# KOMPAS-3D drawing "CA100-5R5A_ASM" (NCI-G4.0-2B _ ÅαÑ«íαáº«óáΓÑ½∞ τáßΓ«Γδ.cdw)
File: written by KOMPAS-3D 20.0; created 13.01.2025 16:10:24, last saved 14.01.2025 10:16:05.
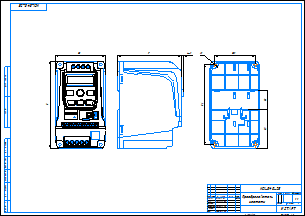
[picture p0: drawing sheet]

Sheet 1: A2, landscape

Document properties: Автор: admin; Полное имя файла: C:\Уралов Работа\Уралов (локальная)\ПЧ\! Китай 3Д-модель NCI\NCI 4.0-7.5 4B\NCI 4.0-7.5 4B.a3d

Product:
- Part/product: CA100-5R5A_ASM
    Масса: 7.13181
    Комментарий: NOT SPECIFIED
  - Component [detail]: CA100-5R5A-SR-01  | Масса: 0.808548; source file: C:\Уралов Работа\Уралов (локальная)\ПЧ\! Китай 3Д-модель NCI\NCI 4.0-7.5 4B\CA100-5R5A-SR-01.m3d
  - Component [detail]: CA100-4R0A-SR-01  | Масса: 0.923365; source file: C:\Уралов Работа\Уралов (локальная)\ПЧ\! Китай 3Д-модель NCI\NCI 4.0-7.5 4B\CA100-4R0A-SR-01.m3d
  - Component [assembly]: QJ_ASM  | Масса: 0.208727; source file: C:\Уралов Работа\Уралов (локальная)\ПЧ\! Китай 3Д-модель NCI\NCI 4.0-7.5 4B\QJ_ASM.a3d
  - Component [assembly]: PCB_ASM  | Масса: 1.9346; source file: C:\Уралов Работа\Уралов (локальная)\ПЧ\! Китай 3Д-модель NCI\NCI 4.0-7.5 4B\PCB_ASM.a3d
  - Component [assembly]: CA100-5R5A-SJ_ASM  | Масса: 1.6976; Комментарий: NOT SPECIFIED; source file: C:\Уралов Работа\Уралов (локальная)\ПЧ\! Китай 3Д-модель NCI\NCI 4.0-7.5 4B\CA100-5R5A-SJ_ASM.a3d
  - Component [assembly]: JIANPAN99_ASM_ASM  | Масса: 0.107178; Комментарий: NOT SPECIFIED; source file: C:\Уралов Работа\Уралов (локальная)\ПЧ\! Китай 3Д-модель NCI\NCI 4.0-7.5 4B\JIANPAN99_ASM_ASM.a3d
  - Component [detail]: CA100-2R2A-SJ-04  | Масса: 0.00516082; source file: C:\Уралов Работа\Уралов (локальная)\ПЧ\! Китай 3Д-модель NCI\NCI 4.0-7.5 4B\CA100-2R2A-SJ-04.m3d
  - Component [detail]: AA  | Масса: 1.44663; source file: C:\Уралов Работа\Уралов (локальная)\ПЧ\! Китай 3Д-модель NCI\NCI 4.0-7.5 4B\AA.m3d

Title block, sheet 1: Наименование: Преобразователь / частоты; designation: NCI-G4.0-2B; Количество листов документа: 1; organisation: INSTART; cell 10: Согласовано; Форматы листов документа: A2; stored path: P:\INSTART\Технический отдел\ОР\Прочие задачи\КД на номенклатурный ряд\КД на типоразмеры ПЧ\NCI\NCI-...-4B\NCI-G4.0_P5.5-4B\NCI-G4.0_P5.5-4B _ Преобразователь частоты.cdw; Разработал: Уралов Д.А.; Проверил: Андреев Н.В.; Подписал: Смелков Ж.Е.; Утвердил: Ефремов И.Н.; Разработал, date: 13.01.25

Views: Вид 1, Проекционный вид 2
Referenced files in C:\Уралов Работа\Уралов (локальная)\ПЧ\! Китай 3Д-модель NCI\NCI 4.0-7.5 4B\: CA100-4R0A-SR-01.m3d, CA100-5R5A-SR-01.m3d, 6025.m3d, QJ_ASM.a3d, QDB.m3d, DRI.m3d, 6912184100XX_MASS.m3d, 6912184100XX_PIN.m3d, 6912184100XX_VIS.m3d, 691218410003.m3d, ASSEM1_ASM.a3d, EU5-03-952_ASM.a3d, QDB_ASM.a3d, 2R2-CM.m3d, EU1_5-14-5_08-00_1_.m3d, LED.m3d, DWQ_2.m3d, ANJIAN.m3d, BM.m3d, 485.m3d, 2R2-CM_ASM.a3d, DRB.m3d, DR.m3d, DRB_ASM.a3d, PCB_ASM.a3d, CA100-5R5A-SJ-01.m3d, CA100-5R5A-SJ-02.m3d, CA100-5R5A-SJ-01-.m3d, CA100-5R5A-SJ_ASM.a3d, CA100-2R2A-SJ-05_45.m3d, CA100-2R2A-SJ-06_23.m3d, CA100-2R2A-SJ-03_22.m3d, JIANPAN99_ASM_17_ASM.a3d, JIANPAN99_ASM_ASM.a3d, CA100-2R2A-SJ-04.m3d, AA.m3d
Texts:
  CA100-4R0A-SR-01
  CA100-4R0A-SR-01 CA100-4R0A-SR-01
  CA100-5R5A-SR-01
  CA100-5R5A-SR-01 CA100-5R5A-SR-01
  QJ_ASM QJ_ASM
  QDB
  QDB QDB
  DRI
  DRI DRI
  6912184100XX_MASS 6912184100XX_MASS
  6912184100XX_PIN 6912184100XX_PIN
  6912184100XX_VIS 6912184100XX_VIS
  ASSEM1_ASM ASSEM1_ASM
  EU5-03-952_ASM
  EU5-03-952_ASM EU5-03-952_ASM
  QDB_ASM QDB_ASM
  EU1_5-14-5_08-00_1_
  EU1_5-14-5_08-00_1_ EU1_5-14-5_08-00_1_
  LED
  LED LED
  DWQ_2 DWQ_2
  ANJIAN
  ANJIAN ANJIAN
  BM BM
  DRB
  DRB DRB
  DR DR
  DRB_ASM DRB_ASM
  PCB_ASM PCB_ASM
  CA100-5R5A-SJ-01
  CA100-5R5A-SJ-01 CA100-5R5A-SJ-01
  CA100-5R5A-SJ-02
  CA100-5R5A-SJ-02 CA100-5R5A-SJ-02
  CA100-5R5A-SJ-01-
  CA100-5R5A-SJ-01- CA100-5R5A-SJ-01-
  CA100-5R5A-SJ_ASM
  CA100-5R5A-SJ_ASM CA100-5R5A-SJ_ASM
  CA100-2R2A-SJ-05_45
  CA100-2R2A-SJ-05_45 CA100-2R2A-SJ-05_45
  CA100-2R2A-SJ-06_23
  CA100-2R2A-SJ-06_23 CA100-2R2A-SJ-06_23
  CA100-2R2A-SJ-03_22
  CA100-2R2A-SJ-03_22 CA100-2R2A-SJ-03_22
  JIANPAN99_ASM_17_ASM JIANPAN99_ASM_17_ASM
  JIANPAN99_ASM_ASM JIANPAN99_ASM_ASM
  Поверхности
  CA100-2R2A-SJ-04
  CA100-2R2A-SJ-04 CA100-2R2A-SJ-04
  AA AA
  CA100-5R5A_ASM
  CA100-5R5A_ASM CA100-5R5A_ASM
Dimensions and other numbers on the sheet: 4±1; 1:1; 1; 13.01.25; 6025; 6025 6025; 2R2-CM; 2R2-CM 2R2-CM; 485; 485 485; 2R2-CM_ASM; 2R2-CM_ASM 2R2-CM_ASM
